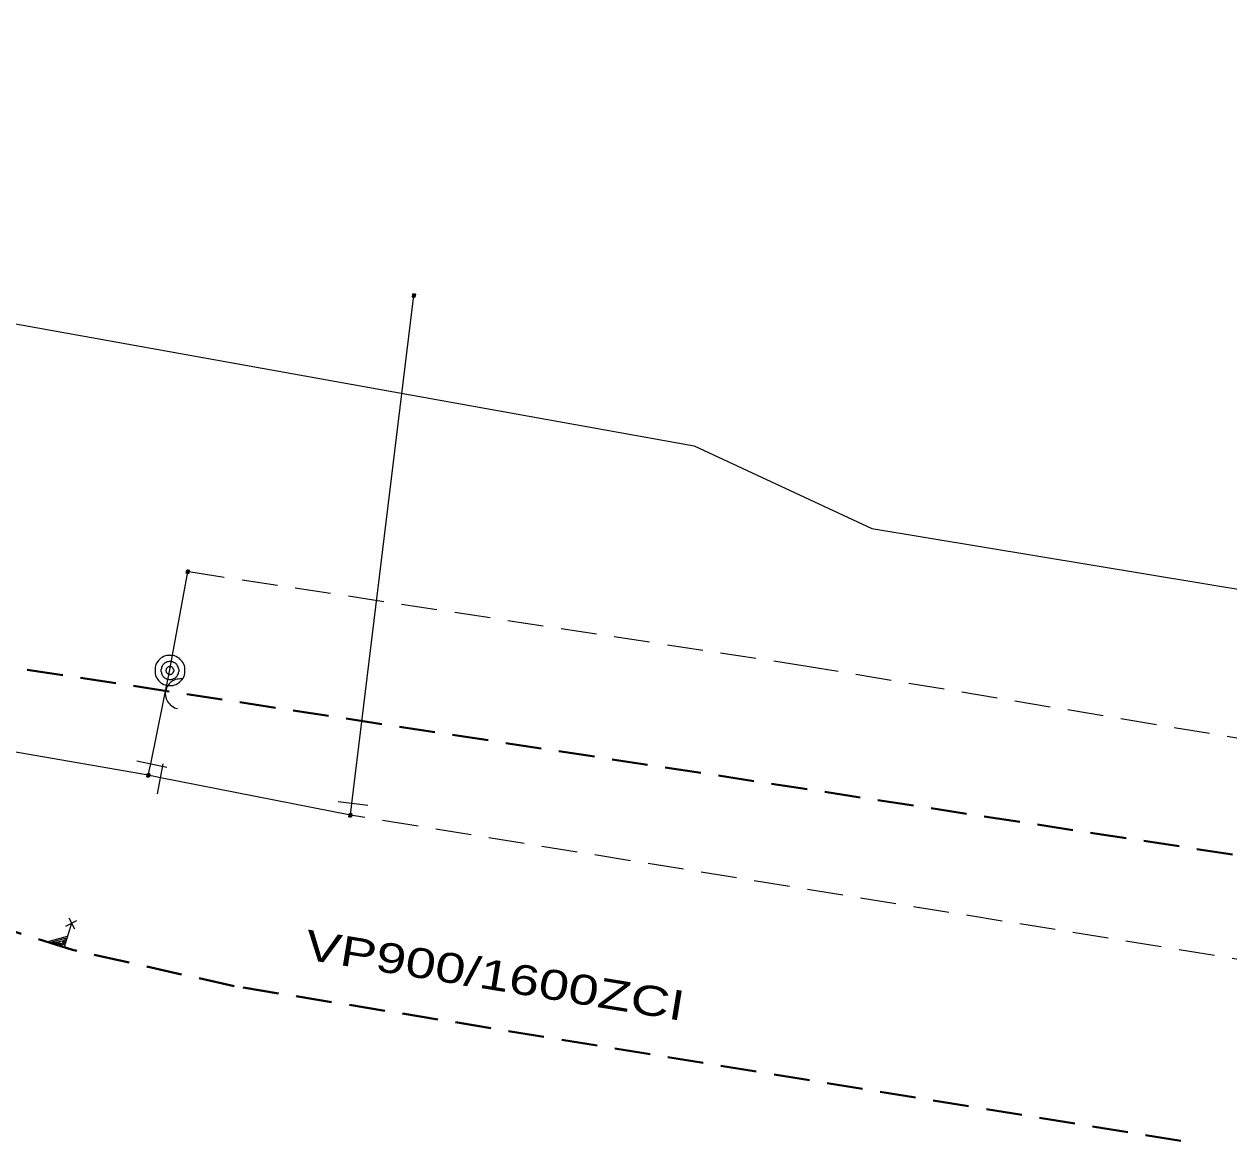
# Model space of a CAD drawing. Extents: x -740851 to -738888, y -1041382 to -1040235.
# Drawn here: x -738996.26 to -738955.94, y -1041347.45 to -1041310.09 of the extents above; entities that cross this region are included whole.
import ezdxf

# ---------------------------------------------------------------- set-up
doc = ezdxf.new("R2010")
doc.units = 0
doc.header["$LTSCALE"] = 0.4
doc.linetypes.add('MEDIUM_DASHED', pattern=[4.5, 3, -1.5])
for name, color, linetype, lineweight in [('18', 7, 'Continuous', 13), ('38', 7, 'Continuous', 13), ('8', 7, 'Continuous', 13)]:
    doc.layers.add(name, color=color, linetype=linetype, lineweight=lineweight)

msp = doc.modelspace()

# ---------------------------------------------------------------- linework, layer by layer
at = {"layer": '18'}
for p, q in [((-738994.859, -1041340.266), (-738994.492, -1041340.073)), ((-738994.761, -1041339.982), (-738994.568, -1041340.354))]:
    msp.add_line(p, q, dxfattribs=at)
at = {"layer": '18', "linetype": 'MEDIUM_DASHED', "lineweight": 40}
msp.add_lwpolyline([(-738957.54, -1041347.45), (-738989.227, -1041342.273), (-738994.634, -1041341.058), (-739000.628, -1041339.172), (-739005.448, -1041337.328), (-739010.163, -1041335.083)], dxfattribs=at)
at = {"layer": '18'}
for points in [[(-738994.668, -1041340.165), (-738994.92, -1041340.966), (-738995.492, -1041340.786), (-738994.806, -1041340.604)], [(-738994.874, -1041340.671), (-738994.947, -1041340.905), (-738995.312, -1041340.79), (-738994.87, -1041340.673)], [(-738994.942, -1041340.742), (-738994.979, -1041340.859), (-738995.166, -1041340.8), (-738994.939, -1041340.743)]]:
    msp.add_lwpolyline(points, dxfattribs=at)
at = {"layer": '38'}
for p, q in [((-738985.29, -1041336.16), (-738983.211, -1041319.173)), ((-738985.338, -1041336.556), (-738985.29, -1041336.16))]:
    msp.add_line(p, q, dxfattribs=at)
at = {"layer": '8'}
for p, q in [((-738983.267, -1041319.215), (-738983.156, -1041319.128)), ((-738983.255, -1041319.116), (-738983.257, -1041319.136)), ((-738983.168, -1041319.228), (-738983.255, -1041319.116)), ((-738983.255, -1041319.116), (-738983.235, -1041319.119)), ((-738983.156, -1041319.128), (-738983.176, -1041319.126)), ((-738983.156, -1041319.128), (-738983.158, -1041319.148)), ((-738983.267, -1041319.215), (-738983.265, -1041319.196)), ((-738983.267, -1041319.215), (-738983.247, -1041319.218)), ((-738983.168, -1041319.228), (-738983.188, -1041319.225)), ((-738983.168, -1041319.228), (-738983.165, -1041319.208)), ((-738990.839, -1041328.45), (-738990.724, -1041328.368)), ((-738990.822, -1041328.351), (-738990.826, -1041328.371)), ((-738990.741, -1041328.466), (-738990.822, -1041328.351)), ((-738990.822, -1041328.351), (-738990.803, -1041328.354)), ((-738990.724, -1041328.368), (-738990.744, -1041328.364)), ((-738990.724, -1041328.368), (-738990.727, -1041328.388)), ((-738990.839, -1041328.45), (-738990.836, -1041328.43)), ((-738990.839, -1041328.45), (-738990.819, -1041328.453)), ((-738990.741, -1041328.466), (-738990.76, -1041328.463)), ((-738990.741, -1041328.466), (-738990.737, -1041328.447)), ((-738991.48, -1041334.953), (-738992.48, -1041334.743)), ((-738991.796, -1041335.84), (-738991.601, -1041334.84)), ((-738992.149, -1041335.269), (-738992.049, -1041335.169)), ((-738992.149, -1041335.169), (-738992.049, -1041335.269)), ((-738992.149, -1041335.169), (-738992.149, -1041335.189)), ((-738992.149, -1041335.169), (-738992.129, -1041335.169)), ((-738992.149, -1041335.269), (-738992.149, -1041335.249)), ((-738992.049, -1041335.169), (-738992.069, -1041335.169)), ((-738992.049, -1041335.169), (-738992.049, -1041335.189)), ((-738992.049, -1041335.269), (-738992.049, -1041335.249)), ((-738992.149, -1041335.269), (-738992.129, -1041335.269)), ((-738992.049, -1041335.269), (-738992.069, -1041335.269)), ((-738984.75, -1041336.225), (-738985.75, -1041336.104)), ((-738985.387, -1041336.605), (-738985.287, -1041336.505)), ((-738985.387, -1041336.505), (-738985.287, -1041336.605)), ((-738985.387, -1041336.505), (-738985.387, -1041336.525)), ((-738985.387, -1041336.505), (-738985.367, -1041336.505)), ((-738985.387, -1041336.605), (-738985.387, -1041336.585)), ((-738985.387, -1041336.605), (-738985.367, -1041336.605)), ((-738985.287, -1041336.505), (-738985.307, -1041336.505)), ((-738985.287, -1041336.605), (-738985.307, -1041336.605)), ((-738985.287, -1041336.505), (-738985.287, -1041336.525)), ((-738985.287, -1041336.605), (-738985.287, -1041336.585))]:
    msp.add_line(p, q, dxfattribs=at)
at = {"layer": '8', "lineweight": 25}
for p, q in [((-738991.39, -1041331.743), (-738990.78, -1041328.41)), ((-738992.02, -1041334.84), (-738991.39, -1041331.743)), ((-738992.1, -1041335.22), (-738992.02, -1041334.84)), ((-738991.69, -1041335.3), (-738992.1, -1041335.22)), ((-738985.338, -1041336.556), (-738991.69, -1041335.3))]:
    msp.add_line(p, q, dxfattribs=at)
at = {"layer": '8', "linetype": 'MEDIUM_DASHED', "lineweight": 25}
msp.add_line((-738936.877, -1041344.419), (-738985.338, -1041336.556), dxfattribs=at)
at = {"layer": '8', "linetype": 'MEDIUM_DASHED', "lineweight": 40}
msp.add_lwpolyline([(-739035.327, -1040869.176), (-739031.896, -1040886.019), (-739019.793, -1040911.158), (-738971.377, -1041006.096), (-738926.048, -1041090.986), (-738916.972, -1041110.384), (-738894.08, -1041157.618), (-738888.006, -1041177.327), (-738893.192, -1041219.807), (-738897.568, -1041245.006), (-738897.033, -1041287.959), (-738895.284, -1041302.914), (-738892.075, -1041339.057), (-738904.789, -1041346.08), (-738934.47, -1041341.14), (-739010.494, -1041329.487), (-739013.151, -1041330.629), (-739014.415, -1041331.172)], dxfattribs=at)
at = {"layer": '8', "lineweight": 25}
for points in [[(-739030.98, -1041327.9), (-739026.78, -1041317.04), (-739010.3, -1041323.4), (-739009.27, -1041324.07), (-739006.93, -1041324.54), (-738999.34, -1041319.61), (-738973.83, -1041324.2), (-738967.89, -1041326.96), (-738912.6, -1041336.12), (-738898.9, -1041324.07), (-738902.59, -1041288.03), (-738903.44, -1041282.07), (-738902.27, -1041277.31), (-738903.16, -1041268.86), (-738902.4, -1041255.6), (-738900.82, -1041237.82), (-738900.46, -1041231.31), (-738900.36, -1041226.7), (-738895.11, -1041221.55), (-738893.11, -1041208.58), (-738893.07, -1041208.11), (-738892.71, -1041202.04)], [(-738992.1, -1041335.22), (-738997.449, -1041334.292), (-738997.96, -1041334.16)]]:
    msp.add_lwpolyline(points, dxfattribs=at)
at = {"layer": '8'}
for points in [[(-738983.205, -1041319.122), (-738983.21, -1041319.122), (-738983.215, -1041319.122), (-738983.221, -1041319.122), (-738983.226, -1041319.124), (-738983.231, -1041319.126), (-738983.235, -1041319.129), (-738983.24, -1041319.131), (-738983.244, -1041319.135), (-738983.248, -1041319.138), (-738983.251, -1041319.142), (-738983.255, -1041319.146), (-738983.257, -1041319.151), (-738983.259, -1041319.156), (-738983.26, -1041319.161), (-738983.261, -1041319.166), (-738983.262, -1041319.171), (-738983.261, -1041319.176), (-738983.261, -1041319.181), (-738983.26, -1041319.186), (-738983.257, -1041319.191), (-738983.255, -1041319.196), (-738983.252, -1041319.2), (-738983.249, -1041319.205), (-738983.245, -1041319.208), (-738983.242, -1041319.212), (-738983.237, -1041319.215), (-738983.232, -1041319.218), (-738983.227, -1041319.219), (-738983.223, -1041319.221), (-738983.218, -1041319.222), (-738983.213, -1041319.222), (-738983.207, -1041319.222), (-738983.202, -1041319.221), (-738983.197, -1041319.22), (-738983.192, -1041319.218), (-738983.188, -1041319.215), (-738983.183, -1041319.213), (-738983.179, -1041319.209), (-738983.175, -1041319.206), (-738983.172, -1041319.202), (-738983.168, -1041319.197), (-738983.166, -1041319.193), (-738983.164, -1041319.188), (-738983.162, -1041319.183), (-738983.162, -1041319.178), (-738983.161, -1041319.173), (-738983.162, -1041319.168), (-738983.162, -1041319.163), (-738983.163, -1041319.158), (-738983.166, -1041319.152), (-738983.168, -1041319.148), (-738983.171, -1041319.144), (-738983.174, -1041319.139), (-738983.178, -1041319.136), (-738983.181, -1041319.132), (-738983.186, -1041319.129), (-738983.191, -1041319.126), (-738983.196, -1041319.124), (-738983.2, -1041319.123)], [(-738990.773, -1041328.359), (-738990.778, -1041328.359), (-738990.783, -1041328.359), (-738990.788, -1041328.359), (-738990.794, -1041328.36), (-738990.799, -1041328.362), (-738990.803, -1041328.364), (-738990.808, -1041328.367), (-738990.812, -1041328.37), (-738990.816, -1041328.373), (-738990.82, -1041328.377), (-738990.824, -1041328.381), (-738990.826, -1041328.386), (-738990.828, -1041328.391), (-738990.83, -1041328.395), (-738990.831, -1041328.4), (-738990.832, -1041328.405), (-738990.832, -1041328.41), (-738990.831, -1041328.415), (-738990.83, -1041328.421), (-738990.828, -1041328.426), (-738990.826, -1041328.431), (-738990.824, -1041328.435), (-738990.82, -1041328.44), (-738990.817, -1041328.443), (-738990.813, -1041328.447), (-738990.809, -1041328.451), (-738990.804, -1041328.454), (-738990.8, -1041328.455), (-738990.795, -1041328.457), (-738990.79, -1041328.458), (-738990.785, -1041328.459), (-738990.78, -1041328.459), (-738990.775, -1041328.459), (-738990.77, -1041328.457), (-738990.764, -1041328.455), (-738990.76, -1041328.453), (-738990.755, -1041328.451), (-738990.751, -1041328.447), (-738990.747, -1041328.444), (-738990.743, -1041328.441), (-738990.74, -1041328.436), (-738990.737, -1041328.432), (-738990.735, -1041328.427), (-738990.733, -1041328.422), (-738990.732, -1041328.417), (-738990.731, -1041328.412), (-738990.732, -1041328.407), (-738990.732, -1041328.402), (-738990.733, -1041328.397), (-738990.735, -1041328.391), (-738990.737, -1041328.387), (-738990.74, -1041328.382), (-738990.743, -1041328.378), (-738990.746, -1041328.374), (-738990.75, -1041328.371), (-738990.754, -1041328.367), (-738990.759, -1041328.364), (-738990.763, -1041328.362), (-738990.768, -1041328.36)], [(-738990.875, -1041331.712), (-738990.875, -1041331.667), (-738990.875, -1041331.606), (-738990.89, -1041331.561), (-738990.905, -1041331.5), (-738990.935, -1041331.455), (-738990.966, -1041331.409), (-738990.996, -1041331.379), (-738991.041, -1041331.334), (-738991.072, -1041331.303), (-738991.117, -1041331.273), (-738991.163, -1041331.243), (-738991.223, -1041331.227), (-738991.269, -1041331.212), (-738991.329, -1041331.212), (-738991.375, -1041331.212), (-738991.435, -1041331.212), (-738991.481, -1041331.212), (-738991.526, -1041331.227), (-738991.587, -1041331.243), (-738991.632, -1041331.273), (-738991.678, -1041331.303), (-738991.708, -1041331.334), (-738991.754, -1041331.379), (-738991.784, -1041331.409), (-738991.814, -1041331.455), (-738991.844, -1041331.5), (-738991.86, -1041331.561), (-738991.875, -1041331.606), (-738991.875, -1041331.667), (-738991.875, -1041331.712), (-738991.875, -1041331.773), (-738991.875, -1041331.818), (-738991.86, -1041331.864), (-738991.844, -1041331.924), (-738991.814, -1041331.97), (-738991.784, -1041332.015), (-738991.754, -1041332.046), (-738991.708, -1041332.091), (-738991.678, -1041332.121), (-738991.632, -1041332.152), (-738991.587, -1041332.182), (-738991.526, -1041332.197), (-738991.481, -1041332.212), (-738991.435, -1041332.212), (-738991.375, -1041332.212), (-738991.329, -1041332.212), (-738991.269, -1041332.212), (-738991.223, -1041332.197), (-738991.163, -1041332.182), (-738991.117, -1041332.152), (-738991.072, -1041332.121), (-738991.041, -1041332.091), (-738990.996, -1041332.046), (-738990.966, -1041332.015), (-738990.935, -1041331.97), (-738990.905, -1041331.924), (-738990.89, -1041331.864), (-738990.875, -1041331.818), (-738990.875, -1041331.773)], [(-738991.072, -1041331.712), (-738991.072, -1041331.682), (-738991.087, -1041331.652), (-738991.087, -1041331.621), (-738991.102, -1041331.591), (-738991.117, -1041331.561), (-738991.132, -1041331.53), (-738991.147, -1041331.515), (-738991.178, -1041331.485), (-738991.193, -1041331.47), (-738991.223, -1041331.455), (-738991.254, -1041331.44), (-738991.284, -1041331.424), (-738991.314, -1041331.424), (-738991.344, -1041331.409), (-738991.375, -1041331.409), (-738991.405, -1041331.409), (-738991.435, -1041331.424), (-738991.466, -1041331.424), (-738991.496, -1041331.44), (-738991.526, -1041331.455), (-738991.557, -1041331.47), (-738991.572, -1041331.485), (-738991.602, -1041331.515), (-738991.617, -1041331.53), (-738991.632, -1041331.561), (-738991.647, -1041331.591), (-738991.663, -1041331.621), (-738991.663, -1041331.652), (-738991.678, -1041331.682), (-738991.678, -1041331.712), (-738991.678, -1041331.743), (-738991.663, -1041331.773), (-738991.663, -1041331.803), (-738991.647, -1041331.834), (-738991.632, -1041331.864), (-738991.617, -1041331.894), (-738991.602, -1041331.909), (-738991.572, -1041331.94), (-738991.557, -1041331.955), (-738991.526, -1041331.97), (-738991.496, -1041331.985), (-738991.466, -1041332), (-738991.435, -1041332), (-738991.405, -1041332.015), (-738991.375, -1041332.015), (-738991.344, -1041332.015), (-738991.314, -1041332), (-738991.284, -1041332), (-738991.254, -1041331.985), (-738991.223, -1041331.97), (-738991.193, -1041331.955), (-738991.178, -1041331.94), (-738991.147, -1041331.909), (-738991.132, -1041331.894), (-738991.117, -1041331.864), (-738991.102, -1041331.834), (-738991.087, -1041331.803), (-738991.087, -1041331.773), (-738991.072, -1041331.743)], [(-738991.238, -1041331.712), (-738991.238, -1041331.697), (-738991.254, -1041331.682), (-738991.254, -1041331.667), (-738991.254, -1041331.652), (-738991.269, -1041331.652), (-738991.269, -1041331.637), (-738991.284, -1041331.621), (-738991.299, -1041331.606), (-738991.314, -1041331.606), (-738991.314, -1041331.591), (-738991.329, -1041331.591), (-738991.344, -1041331.591), (-738991.36, -1041331.576), (-738991.375, -1041331.576), (-738991.39, -1041331.576), (-738991.405, -1041331.591), (-738991.42, -1041331.591), (-738991.435, -1041331.591), (-738991.435, -1041331.606), (-738991.451, -1041331.606), (-738991.466, -1041331.621), (-738991.481, -1041331.637), (-738991.496, -1041331.652), (-738991.496, -1041331.667), (-738991.496, -1041331.682), (-738991.511, -1041331.697), (-738991.511, -1041331.712), (-738991.511, -1041331.727), (-738991.496, -1041331.743), (-738991.496, -1041331.758), (-738991.496, -1041331.773), (-738991.481, -1041331.788), (-738991.466, -1041331.803), (-738991.451, -1041331.818), (-738991.435, -1041331.834), (-738991.42, -1041331.834), (-738991.405, -1041331.834), (-738991.39, -1041331.849), (-738991.375, -1041331.849), (-738991.36, -1041331.849), (-738991.344, -1041331.834), (-738991.329, -1041331.834), (-738991.314, -1041331.834), (-738991.299, -1041331.818), (-738991.284, -1041331.803), (-738991.269, -1041331.788), (-738991.269, -1041331.773), (-738991.254, -1041331.773), (-738991.254, -1041331.758), (-738991.254, -1041331.743), (-738991.238, -1041331.727)], [(-738992.049, -1041335.219), (-738992.049, -1041335.214), (-738992.05, -1041335.209), (-738992.051, -1041335.204), (-738992.053, -1041335.199), (-738992.056, -1041335.194), (-738992.059, -1041335.19), (-738992.062, -1041335.186), (-738992.066, -1041335.182), (-738992.07, -1041335.179), (-738992.074, -1041335.176), (-738992.079, -1041335.173), (-738992.084, -1041335.171), (-738992.089, -1041335.17), (-738992.094, -1041335.169), (-738992.099, -1041335.169), (-738992.104, -1041335.169), (-738992.109, -1041335.17), (-738992.114, -1041335.171), (-738992.119, -1041335.173), (-738992.124, -1041335.176), (-738992.128, -1041335.179), (-738992.132, -1041335.182), (-738992.136, -1041335.186), (-738992.139, -1041335.19), (-738992.142, -1041335.194), (-738992.145, -1041335.199), (-738992.147, -1041335.204), (-738992.148, -1041335.209), (-738992.149, -1041335.214), (-738992.149, -1041335.219), (-738992.149, -1041335.224), (-738992.148, -1041335.229), (-738992.147, -1041335.234), (-738992.145, -1041335.239), (-738992.142, -1041335.244), (-738992.139, -1041335.248), (-738992.136, -1041335.252), (-738992.132, -1041335.256), (-738992.128, -1041335.259), (-738992.124, -1041335.262), (-738992.119, -1041335.265), (-738992.114, -1041335.267), (-738992.109, -1041335.268), (-738992.104, -1041335.269), (-738992.099, -1041335.269), (-738992.094, -1041335.269), (-738992.089, -1041335.268), (-738992.084, -1041335.267), (-738992.079, -1041335.265), (-738992.074, -1041335.262), (-738992.07, -1041335.259), (-738992.066, -1041335.256), (-738992.062, -1041335.252), (-738992.059, -1041335.248), (-738992.056, -1041335.244), (-738992.053, -1041335.239), (-738992.051, -1041335.234), (-738992.05, -1041335.229), (-738992.049, -1041335.224)], [(-738985.287, -1041336.555), (-738985.287, -1041336.55), (-738985.288, -1041336.545), (-738985.289, -1041336.54), (-738985.291, -1041336.535), (-738985.294, -1041336.53), (-738985.297, -1041336.526), (-738985.3, -1041336.522), (-738985.304, -1041336.518), (-738985.308, -1041336.515), (-738985.312, -1041336.512), (-738985.317, -1041336.509), (-738985.322, -1041336.507), (-738985.327, -1041336.506), (-738985.332, -1041336.505), (-738985.337, -1041336.505), (-738985.342, -1041336.505), (-738985.347, -1041336.506), (-738985.352, -1041336.507), (-738985.357, -1041336.509), (-738985.362, -1041336.512), (-738985.366, -1041336.515), (-738985.37, -1041336.518), (-738985.374, -1041336.522), (-738985.377, -1041336.526), (-738985.38, -1041336.53), (-738985.383, -1041336.535), (-738985.385, -1041336.54), (-738985.386, -1041336.545), (-738985.387, -1041336.55), (-738985.387, -1041336.555), (-738985.387, -1041336.56), (-738985.386, -1041336.565), (-738985.385, -1041336.57), (-738985.383, -1041336.575), (-738985.38, -1041336.58), (-738985.377, -1041336.584), (-738985.374, -1041336.588), (-738985.37, -1041336.592), (-738985.366, -1041336.595), (-738985.362, -1041336.598), (-738985.357, -1041336.601), (-738985.352, -1041336.603), (-738985.347, -1041336.604), (-738985.342, -1041336.605), (-738985.337, -1041336.605), (-738985.332, -1041336.605), (-738985.327, -1041336.604), (-738985.322, -1041336.603), (-738985.317, -1041336.601), (-738985.312, -1041336.598), (-738985.308, -1041336.595), (-738985.304, -1041336.592), (-738985.3, -1041336.588), (-738985.297, -1041336.584), (-738985.294, -1041336.58), (-738985.291, -1041336.575), (-738985.289, -1041336.57), (-738985.288, -1041336.565), (-738985.287, -1041336.56)]]:
    msp.add_lwpolyline(points, close=True, dxfattribs=at)
at = {"layer": '8', "linetype": 'MEDIUM_DASHED', "lineweight": 25}
msp.add_lwpolyline([(-738894.34, -1041344.88), (-738894.942, -1041344.964), (-738924.632, -1041339.168), (-738969.983, -1041331.586), (-738990.78, -1041328.41)], dxfattribs=at)
at = {"layer": '8'}
msp.add_lwpolyline([(-738990.93, -1041331.997), (-738990.982, -1041331.997), (-738991.031, -1041331.988), (-738991.085, -1041331.998), (-738991.138, -1041332.008), (-738991.192, -1041332.018), (-738991.237, -1041332.04), (-738991.282, -1041332.062), (-738991.33, -1041332.093), (-738991.367, -1041332.127), (-738991.405, -1041332.161), (-738991.434, -1041332.206), (-738991.464, -1041332.252), (-738991.494, -1041332.298), (-738991.503, -1041332.347), (-738991.523, -1041332.395), (-738991.523, -1041332.446), (-738991.533, -1041332.496), (-738991.523, -1041332.549), (-738991.512, -1041332.603), (-738991.502, -1041332.656), (-738991.481, -1041332.702), (-738991.459, -1041332.747), (-738991.427, -1041332.794), (-738991.393, -1041332.832), (-738991.359, -1041332.869), (-738991.314, -1041332.899), (-738991.268, -1041332.929), (-738991.222, -1041332.958), (-738991.173, -1041332.968), (-738991.125, -1041332.988)], dxfattribs=at)

# ---------------------------------------------------------------- texts
at = {"layer": '18', "width": 1.35}
msp.add_text('VP900/1600ZCI', height=1, rotation=350.721, dxfattribs=at).set_placement((-738986.921, -1041341.365))

doc.saveas('drawing.dxf')
